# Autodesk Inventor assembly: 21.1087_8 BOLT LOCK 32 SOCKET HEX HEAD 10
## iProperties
Created: 2007-03
Part Number: 21.1087_8 BOLT LOCK 32 SOCKET HEX HEAD 10
Document SubType Name: Assembly
Designer: Andy Moles
Author: Andy Moles
